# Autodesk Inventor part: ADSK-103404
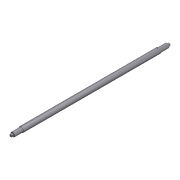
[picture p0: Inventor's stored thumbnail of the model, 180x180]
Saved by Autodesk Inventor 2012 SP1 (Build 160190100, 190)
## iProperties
Shininess: 0.0
Created: 2000-11
Part Number: ADSK-103404
Document SubType Name: Modeling
Stock Number: ADSK-103404
Density: 1 g/cm^3
Material: Default
Density: 0.0
Volumn: 0.0
Area: 0.0
PropertySet Name: Model Information
Control State: 0
Master: False
Checked Out: False
Author: gao
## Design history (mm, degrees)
node "Extrusion1" dims "d1" = 1930.4, "d2" = 0
  sketch "Sketch1"
    geometry: C1 r 37.306 at (0, 0)
    constraints: 1 centre point
    dimensions: "d0" = 74.6125 diameter of C1
node "Extrusion2" dims "d4" = 120.015, "d5" = 0
  sketch "Sketch2"
    geometry: C1 r 37.306 at (0, 0) reference; C2 r 31.75 at (0, 0)
    constraints: 1 centre point, 1 coincident
    dimensions: "d3" = 63.5 diameter of C2
workplane "Work Plane1"
node "Fillet1" dims "d20" = 6.35
node "Extrusion5" dims "d26" = 28, "d27" = 0
  sketch "Sketch5"
    geometry: L1 (-15, 15)-(15, 15); L2 (15, 15)-(15, -15); L3 (15, -15)-(-15, -15); L4 (-15, -15)-(-15, 15); C1 r 25.4 at (0, 0) reference
    constraints: 8 end point, 2 parallel, 1 horizontal, 1 perpendicular
    dimensions: "d22" = 30 distance of L2.end L3.end; "d23" = 30 distance of L3.end L1.start; "d24" = 15 distance from line of L4 C1.centre; "d25" = 15 distance from line of L3 C1.centre
node "Chamfer3" dims "d28" = 1.524, "d29" = 1.524, "d41" = 45 deg
node "Mirror2"
node "Fillet3" dims "d30" = 1.524
node "Fillet4" dims "d31" = 6.35
node "Chamfer4" dims "d32" = 1.524, "d33" = 1.524, "d42" = 45 deg
workplane "Work Plane3"
node "Hole1" dims "d35" = 12.7, "d36" = 9.525, "d37" = 6.35, "d38" = 60 deg, "d39" = 19.05, "d40" = 118 deg
  sketch "Sketch6"
    geometry: L1 (35.782, 0)-(-35.782, 0) reference; 1 further point
    dimensions: "d34" = 19.05 distance from line of point (0, 19.05) L1
body "Solid1"
other parameters: "d9" = -965.2 (= -0.5 x d1)
